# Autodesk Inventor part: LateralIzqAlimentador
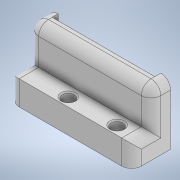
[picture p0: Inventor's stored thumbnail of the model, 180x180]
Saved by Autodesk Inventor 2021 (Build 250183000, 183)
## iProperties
Created: 2021-02
Part Number: LateralIzqAlimentador
Material: Genérico
Document SubType Name: Modeling
Designer: ATOUZA
Density: 1 g/cm^3
Appearance: Valor por defecto
Author: ATOUZA
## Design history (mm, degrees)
node "Plano de trabajo1"
sketch "Boceto1"
  geometry: L1 (25, 25.5)-(-25, 25.5); L2 (-25, 25.5)-(-25, 17.5); L3 (-25, 17.5)-(-21, 17.5); L4 (-21, 17.5)-(-21, 20); L5 (25, 25.5)-(25, 17.5); L6 (25, 17.5)-(21, 17.5); L7 (21, 17.5)-(21, 20); L8 (25, 25.5)-(-25, 25.5); L9 (-21, 20)-(21, 20); 1 further point
  constraints: 18 end point, 3 horizontal, 3 parallel, 1 perpendicular, 1 point on line
  dimensions: "d1" = 4 distance of L3.end L2.end; "d2" = 4 distance of L5.end L6.end; "d3" = 8 distance of L1.start L5.end; "d4" = 50 distance of L1.start L1.end; "d38" = 2.5 distance of L6.end L7.end; "d39" = 42 distance of L4.end L7.end
extrude "Extrusión2" new body sketch "Boceto1" distance "d17" = 25; taper "d18" = 0 deg
sketch "Boceto4"
  geometry: L1 (-25, 25.5)-(25, 25.5) reference; L2 (25, 25.5)-(-25, 25.5); L3 (-25, 25.5)-(-25, 33.5); L4 (-25, 33.5)-(25, 33.5); L5 (25, 33.5)-(25, 25.5); L6 (-21, 17.5)-(-21, 20) reference; L7 (-21, 20)-(19, 20); L8 (19, 20)-(19, -20); L9 (19, -20)-(-21, -20); L10 (-21, -20)-(-21, 20); L11 (0, -0.5)-(0, 29.5); L12 (0, 29.5)-(-25, 29.5); L13 (0, 29.5)-(25, 29.5); C1 r 2 at (-12.5, 29.5); C2 r 2 at (12.5, 29.5); 1 further point
  constraints: 22 end point, 4 midpoint, 4 parallel, 2 centre point, 2 horizontal, 2 perpendicular, 1 vertical
  dimensions: "d19" = 8 distance of L2.end L3.end; "d22" = 40 distance of L8.end L9.end; "d23" = 40 distance of L7.end L8.end; "d26" = 30 distance of L11.start L11.end; "d27" = 4 diameter of C1; "d28" = 4 diameter of C2
extrude "Extrusión3" join sketch "Boceto4" distance "d20" = 10; taper "d21" = 0 deg
sketch "Boceto5"
  geometry: L1 (-25, -33.5)-(25, -33.5) reference; L2 (-25, -25.5)-(25, -25.5) reference; L3 (6, -29.893)-(-15, -29.893); L4 (6, -29.893)-(25, -29.893); L5 (25, -17.5)-(25, -33.5) reference; L6 (4.811, 50.86)-(5.011, 50.86) reference; L7 (-4.5, -429.14)-(-4.5, 50.86) reference; L8 (15.5, -429.14)-(15.5, 50.86) reference; 3 further points
  constraints: 4 end point, 3 point on line, 2 horizontal, 2 midpoint
hole "Agujero2" sketch "Boceto5" diameter "d29" = 5; stored, may be unused: countersink angle "d33" = 90 deg, drill point angle "d35" = 118 deg; dims "d30" = 6, "d31" = 6, "d32" = 2, "d34" = 8
fillet "Empalme1" dims "d37" = 4
node "Sólido2"
node "Referencia3"
node "Referencia4"
node "Referencia5"
